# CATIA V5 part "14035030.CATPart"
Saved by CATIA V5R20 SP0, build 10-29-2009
Part number: 14035030
Definition: NONE
Nomenclature: 14035030
Source: Unknown
Description: 14035030
Bounding box of the stored display mesh (mm): x -15 to 60, y -31.5 to 21.6, z -21.6 to 21.6
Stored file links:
  C:\Users\Utente\Desktop\IO LAVORO\3D X SITO CF\X SITO\PLASTICA\RF2\14035030.CATPart
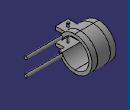
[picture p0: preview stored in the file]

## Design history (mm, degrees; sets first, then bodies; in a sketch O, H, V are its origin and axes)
Body1 "14035030" (main body)
  Solid1: solid without history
